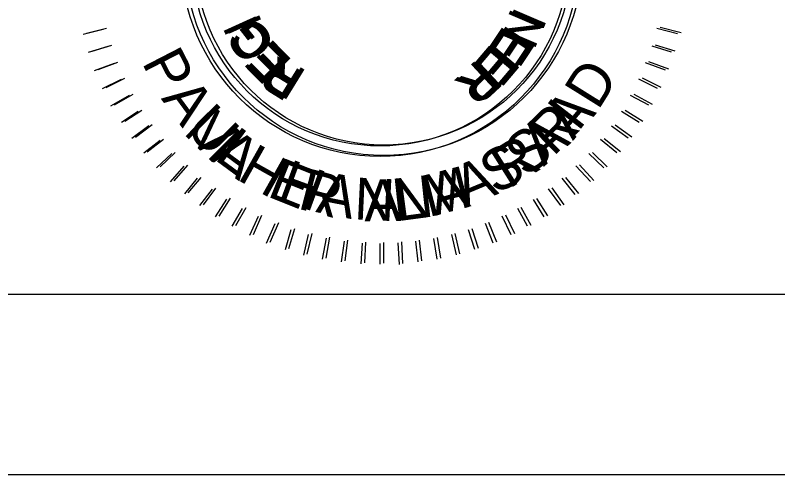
# Model space of a CAD drawing. Extents: x -16 to 5016, y -5 to 5003.
# Drawn here: x 26.289 to 28.397, y -2.37 to -1.099 of the extents above; entities that cross this region are included whole.
import ezdxf

# ---------------------------------------------------------------- set-up
doc = ezdxf.new("R2010")
doc.units = 0
for name, color, linetype in [('RD_SHT_Bndy', 7, 'Continuous'), ('RD_SHT_IplotShp', 7, 'Continuous'), ('RD_SHT_Misc1', 7, 'Continuous'), ('RD_SHT_SEAL_DR', 7, 'Continuous'), ('RD_SHT_SEAL_MA', 7, 'Continuous'), ('RD_SHT_Snap', 7, 'Continuous')]:
    doc.layers.add(name, color=color, linetype=linetype)

msp = doc.modelspace()

# ---------------------------------------------------------------- linework, layer by layer
at = {"layer": 'RD_SHT_Bndy'}
for p, q in [((0, -1.87), (33.5, -1.87)), ((33.771, -2.37), (-1.429, -2.37))]:
    msp.add_line(p, q, dxfattribs=at)
at = {"layer": 'RD_SHT_IplotShp'}
msp.add_lwpolyline([(-2.129, 19.63), (33.871, 19.63), (33.871, -2.37), (-2.129, -2.37)], close=True, dxfattribs=at)
at = {"layer": 'RD_SHT_Misc1'}
msp.add_lwpolyline([(33.7703, -2.37), (33.771, 19.63), (-0.229, 19.631), (-0.2297, -2.369)], close=True, dxfattribs=at)
at = {"layer": 'RD_SHT_SEAL_DR'}
for p, q in [((26.4861, -1.1486), (26.5412, -1.1346)), ((28.1299, -1.1475), (28.0727, -1.1324)), ((26.5013, -1.1982), (26.5553, -1.181)), ((28.1137, -1.1982), (28.0597, -1.181)), ((26.5175, -1.249), (26.5725, -1.2285)), ((28.0964, -1.2479), (28.0413, -1.2274)), ((26.5401, -1.2987), (26.592, -1.2728)), ((28.0749, -1.2987), (28.023, -1.2727)), ((26.5628, -1.3462), (26.6147, -1.3172)), ((28.051, -1.3452), (28.0003, -1.3182)), ((26.592, -1.3916), (26.6385, -1.3613)), ((28.0241, -1.3927), (27.9755, -1.3625)), ((26.6211, -1.4359), (26.6676, -1.4013)), ((27.9938, -1.4358), (27.9474, -1.4023)), ((26.6535, -1.4769), (26.699, -1.4413)), ((27.9625, -1.4769), (27.9172, -1.4402)), ((26.6892, -1.518), (26.7313, -1.478)), ((27.9258, -1.5179), (27.8848, -1.478)), ((26.728, -1.5568), (26.7659, -1.5136)), ((27.889, -1.5557), (27.8491, -1.5126)), ((26.767, -1.5903), (26.8026, -1.5472)), ((27.847, -1.5914), (27.8113, -1.5472)), ((26.809, -1.6227), (26.8436, -1.5773)), ((27.807, -1.6227), (27.7735, -1.5762)), ((26.8522, -1.6541), (26.8836, -1.6043)), ((27.7616, -1.654), (27.7314, -1.6054)), ((26.8987, -1.68), (26.9268, -1.6303)), ((27.7152, -1.68), (27.6882, -1.6302)), ((26.9474, -1.7048), (26.971, -1.6519)), ((27.6699, -1.7037), (27.645, -1.6518)), ((26.9937, -1.7264), (27.0175, -1.6724)), ((27.6201, -1.7264), (27.5985, -1.6724)), ((27.0455, -1.7437), (27.0618, -1.6886)), ((27.0963, -1.7599), (27.1094, -1.7027)), ((27.5186, -1.7588), (27.5057, -1.7026)), ((27.5694, -1.7437), (27.5521, -1.6897)), ((27.1482, -1.7707), (27.159, -1.7123)), ((27.2011, -1.7782), (27.2087, -1.721)), ((27.2551, -1.7837), (27.2583, -1.7264)), ((27.308, -1.7847), (27.308, -1.7275)), ((27.361, -1.7858), (27.3577, -1.7253)), ((27.4128, -1.7782), (27.4063, -1.721)), ((27.4657, -1.7707), (27.456, -1.7135))]:
    msp.add_line(p, q, dxfattribs=at)
for radius in [0.5496, 0.5207]:
    msp.add_circle((27.3074, -0.9369), radius, dxfattribs=at)
at = {"layer": 'RD_SHT_SEAL_MA'}
for p, q in [((26.4763, -1.1513), (26.5314, -1.1372)), ((28.1201, -1.1502), (28.0628, -1.1351)), ((26.4915, -1.2009), (26.5455, -1.1837)), ((28.1039, -1.2009), (28.0499, -1.1837)), ((26.5077, -1.2517), (26.5628, -1.2312)), ((28.0867, -1.2506), (28.0316, -1.2301)), ((26.5303, -1.3013), (26.5822, -1.2754)), ((28.065, -1.3013), (28.0132, -1.2754)), ((26.553, -1.3489), (26.6048, -1.3198)), ((28.0413, -1.3478), (27.9905, -1.3208)), ((26.5822, -1.3943), (26.6287, -1.364)), ((28.0143, -1.3953), (27.9657, -1.3651)), ((26.6113, -1.4385), (26.6578, -1.404)), ((27.984, -1.4385), (27.9376, -1.4051)), ((26.6438, -1.4796), (26.6891, -1.4439)), ((27.9528, -1.4796), (27.9073, -1.4428)), ((26.6794, -1.5206), (26.7215, -1.4807)), ((27.916, -1.5206), (27.8749, -1.4807)), ((26.7183, -1.5595), (26.7561, -1.5163)), ((27.8793, -1.5584), (27.8393, -1.5152)), ((26.7572, -1.593), (26.7928, -1.5498)), ((27.8372, -1.5941), (27.8015, -1.5498)), ((26.7993, -1.6253), (26.8338, -1.58)), ((27.7972, -1.6253), (27.7638, -1.5789)), ((26.8425, -1.6567), (26.8738, -1.607)), ((27.7518, -1.6567), (27.7216, -1.6081)), ((26.8889, -1.6826), (26.917, -1.6329)), ((27.7054, -1.6826), (27.6784, -1.6329)), ((26.9375, -1.7074), (26.9613, -1.6545)), ((27.66, -1.7063), (27.6352, -1.6545)), ((26.9839, -1.7291), (27.0078, -1.6751)), ((27.6103, -1.7291), (27.5888, -1.6751)), ((27.0358, -1.7463), (27.052, -1.6913)), ((27.0866, -1.7625), (27.0995, -1.7053)), ((27.5088, -1.7614), (27.4958, -1.7053)), ((27.5596, -1.7463), (27.5423, -1.6923)), ((27.1384, -1.7733), (27.1492, -1.715)), ((27.1913, -1.7809), (27.1988, -1.7237)), ((27.2453, -1.7863), (27.2486, -1.7291)), ((27.3512, -1.7884), (27.3479, -1.728)), ((27.403, -1.7809), (27.3965, -1.7237)), ((27.4559, -1.7733), (27.4462, -1.7161)), ((27.2983, -1.7873), (27.2983, -1.7301))]:
    msp.add_line(p, q, dxfattribs=at)
for radius in [0.5496, 0.5207]:
    msp.add_circle((27.2976, -0.9395), radius, dxfattribs=at)
at = {"layer": 'RD_SHT_Snap'}
msp.add_lwpolyline([(-1.899, 19.63), (34.101, 19.63), (34.101, -2.37), (-1.899, -2.37)], close=True, dxfattribs=at)

# ---------------------------------------------------------------- texts
at = {"layer": 'RD_SHT_SEAL_DR'}
for s, height, rotation, p in [('N', 0.0963, 246.8176, (27.6717, -1.073)), ('I', 0.0964, 114.4014, (26.9732, -1.1206)), ('G', 0.0964, 127.9775, (27.0132, -1.1777)), ('E', 0.0963, 236.4563, (27.6502, -1.1212)), ('E', 0.0964, 134.7656, (27.0575, -1.2253)), ('E', 0.0963, 229.6708, (27.616, -1.1721)), ('P', 0.1157, 297.3177, (26.6374, -1.2288)), ('R', 0.0964, 148.3418, (27.0975, -1.2544)), ('R', 0.0963, 222.8852, (27.5759, -1.2166)), ('D', 0.1157, 58.0167, (27.9004, -1.364)), ('A', 0.1157, 306.2426, (26.6908, -1.3292)), ('A', 0.1157, 49.5168, (27.8308, -1.447)), ('U', 0.1157, 314.7425, (26.7555, -1.416)), ('L', 0.1157, 323.6675, (26.8365, -1.4958)), ('A', 0.1157, 41.0169, (27.7497, -1.5187)), ('R', 0.1157, 32.0919, (27.654, -1.5803)), ('H', 0.1157, 339.8173, (27.0106, -1.6047)), ('A', 0.1157, 348.7423, (27.1178, -1.6427)), ('A', 0.1157, 15.0921, (27.4508, -1.6535)), ('N', 0.1157, 357.2422, (27.2242, -1.663)), ('N', 0.1157, 6.1671, (27.3379, -1.6671))]:
    msp.add_text(s, height=height, rotation=rotation, dxfattribs=at).set_placement(p)
at = {"layer": 'RD_SHT_SEAL_MA'}
for s, height, rotation, p in [('N', 0.0963, 246.8171, (27.6616, -1.0759)), ('I', 0.0964, 114.4009, (26.963, -1.1234)), ('G', 0.0964, 127.9771, (27.003, -1.1807)), ('E', 0.0963, 236.4559, (27.6399, -1.1241)), ('E', 0.0964, 134.7652, (27.0473, -1.2282)), ('E', 0.0963, 229.6703, (27.6058, -1.1749)), ('R', 0.0964, 148.3414, (27.0873, -1.2573)), ('R', 0.0963, 222.8848, (27.5657, -1.2194)), ('I', 0.1157, 52.2473, (27.8445, -1.424)), ('M', 0.1157, 315.3231, (26.7507, -1.4241)), ('R', 0.1157, 44.7366, (27.7765, -1.4913)), ('S', 0.1157, 37.2258, (27.7003, -1.5492)), ('A', 0.1157, 323.5491, (26.8256, -1.4973)), ('H', 0.1157, 330.7022, (26.8988, -1.5518)), ('S', 0.1157, 29.7151, (27.6171, -1.5966)), ('E', 0.1157, 338.2129, (26.9822, -1.5986)), ('M', 0.1157, 14.336, (27.4314, -1.6578)), ('A', 0.1157, 22.562, (27.5328, -1.6313)), ('R', 0.1157, 345.366, (27.0667, -1.6328)), ('A', 0.1157, 0.3875, (27.2543, -1.6689)), ('L', 0.1157, 7.5405, (27.3455, -1.6686))]:
    msp.add_text(s, height=height, rotation=rotation, dxfattribs=at).set_placement(p)

doc.saveas('drawing.dxf')
